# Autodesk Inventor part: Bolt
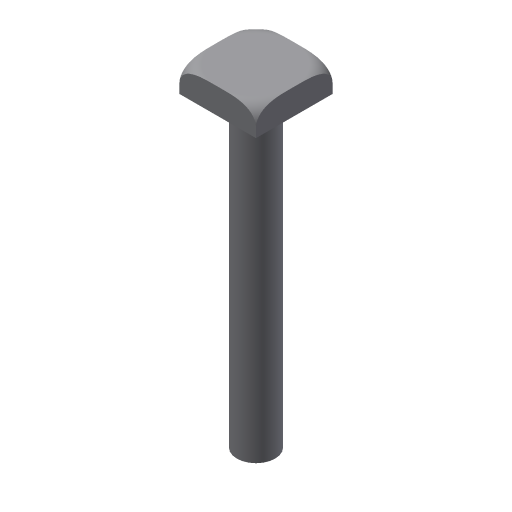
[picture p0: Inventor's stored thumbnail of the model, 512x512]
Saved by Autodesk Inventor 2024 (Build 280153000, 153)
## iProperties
Created: 2009-04
Part Number: Bolt
Document SubType Name: Modeling
Designer: Sham
Density: 1 g/cm^3
Material: Generic
Appearance: Default
Mass: 15.4123 g
Surface Area: 54.8695 cm^2
Volume: 15.4123 cm^3
Author: Sham
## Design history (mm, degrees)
sketch "Sketch1"
  geometry: L1 (-12, 12)-(12, 12); L2 (12, 12)-(12, -12); L3 (12, -12)-(-12, -12); L4 (-12, -12)-(-12, 12); 1 further point
  constraints: 8 end point, 2 parallel, 2 perpendicular, 1 horizontal, 1 other
  dimensions: "d0" = 24 distance of L1.start L1.end; "d1" = 12 distance from line of L2 point (0, 0); "d2" = 12 distance from line of L1 point (0, 0)
extrude "Extrusion1" new body sketch "Sketch1" distance "d3" = 8; taper "d4" = 0 deg
sketch "Sketch2"
  geometry: C1 r 6 at (0, 0)
  constraints: 1 centre point
  dimensions: "d5" = 12 diameter of C1
extrude "Extrusion2" join sketch "Sketch2" distance "d6" = 96; taper "d7" = 0 deg
workpoint "Work Point1"
workplane "Work Plane1"
sketch "Sketch3"
  geometry: L1 (33.941, 5)-(33.941, 6); L2 (28.941, 0)-(28.405, 0); L3 (16.971, 125.007)-(16.971, -22.043) reference; A1 r 5 centre (28.941, 5) between (28.941, 0) and (33.941, 5); 1 further point
  constraints: 4 end point, 2 point on circle, 2 point on line, 2 tangent, 1 centre point, 1 perpendicular
  dimensions: "d10" = 5 radius of A1
revolve "Revolution1" sketch "Sketch3" stored, may be unused: angle "d12" = 90 deg
body "Solid1"
other parameters: "d11" = 90 deg
